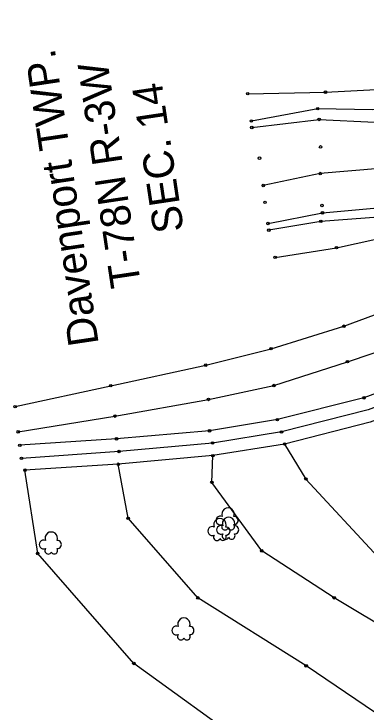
# Model space of a CAD drawing. Extents: x 21481721 to 21494985, y 8063982 to 8084842.
# Drawn here: x 21487805.3 to 21487944.9, y 8075079.6 to 8075356.1 of the extents above; entities that cross this region are included whole.
import ezdxf

# ---------------------------------------------------------------- set-up
doc = ezdxf.new("R2010")
doc.units = 0
for name, color, linetype in [('EXT_BL', 7, 'Continuous'), ('EXT_BNK', 7, 'Continuous'), ('EXT_C', 7, 'Continuous'), ('EXT_DU', 7, 'Continuous'), ('EXT_EP', 7, 'Continuous'), ('EXT_EW', 7, 'Continuous'), ('SurNaturalCells', 7, 'Continuous'), ('SurSurveyPoints', 7, 'Continuous'), ('Text', 7, 'Continuous')]:
    doc.layers.add(name, color=color, linetype=linetype)

msp = doc.modelspace()

# ---------------------------------------------------------------- linework, layer by layer
at = {"layer": 'EXT_BL'}
for points in [[(21487899.65, 8075311.12), (21487926.31, 8075314.33), (21487948.47, 8075313.19), (21487977.99, 8075319.96), (21488001.76, 8075319.05), (21488031.54, 8075324.07), (21488042.97, 8075326.03), (21488043.27, 8075340.95)], [(21487906.07, 8075273.12), (21487927.64, 8075277.31), (21487950.95, 8075279.4), (21487980.9, 8075284.8), (21488008.68, 8075286.71), (21488029.4, 8075287.81), (21488058.97, 8075290.19), (21488075.16, 8075293.91), (21488088.3, 8075291.86), (21488106.39, 8075293.3), (21488126.3, 8075293.36), (21488151.15, 8075297.33), (21488159.73, 8075298.37), (21488161.94, 8075298.12), (21488175.34, 8075296.97), (21488196.46, 8075301.74), (21488221.52, 8075304.21), (21488248.96, 8075305.15), (21488267.9, 8075305.62), (21488289.28, 8075304.94), (21488307.44, 8075304.08)], [(21487805.81, 8075200.57), (21487843.69, 8075208.86), (21487881.33, 8075216.99), (21487907.27, 8075223.5), (21487936.1, 8075232.4), (21487962.88, 8075242.3)], [(21487807.01, 8075190.56), (21487845.36, 8075196.81), (21487882.48, 8075203.41), (21487908.34, 8075208.9), (21487937.56, 8075218.37), (21487967.71, 8075228.44)], [(21487912.64, 8075185.75), (21487921.08, 8075171.87), (21487949.76, 8075140.97), (21487968.9, 8075133.2), (21487985.64, 8075128.01), (21488002.28, 8075121.82), (21488028.81, 8075113.01), (21488056.18, 8075112.57), (21488095.4, 8075114.28)], [(21488096.33, 8075080.43), (21488058.31, 8075085.68), (21488028.39, 8075089.85), (21487994.89, 8075100.27), (21487957.6, 8075109.66), (21487932.27, 8075124.86), (21487903.55, 8075143.43), (21487883.81, 8075170.57), (21487884.18, 8075181.16)], [(21488104.12, 8075053.16), (21488060.1, 8075057.21), (21488026.96, 8075060.99), (21487993.7, 8075067.26), (21487956.42, 8075073.93), (21487921.18, 8075097.88), (21487878.26, 8075124.79), (21487850.62, 8075156.33), (21487846.7, 8075177.74)], [(21488104, 8075024.19), (21488085.19, 8075025.67), (21488052.36, 8075029.9), (21488025.25, 8075031.54), (21487992.49, 8075034.52), (21487979.79, 8075035.75), (21487938.6, 8075047.85), (21487899.23, 8075065.23), (21487852.86, 8075098.85), (21487814.73, 8075142.38), (21487809.68, 8075175.41)]]:
    msp.add_lwpolyline(points, dxfattribs=at)
at = {"layer": 'EXT_BNK'}
for points in [[(21487898.01, 8075324.5), (21487928.88, 8075325.11), (21487948.89, 8075326.16), (21487970.53, 8075330.86), (21487994.52, 8075331.44), (21488017.06, 8075333.54), (21488035.32, 8075334.91), (21488036.46, 8075343.25), (21488040.24, 8075349.55), (21488050.96, 8075348.42), (21488057.24, 8075339.77), (21488065.83, 8075341.83), (21488068.85, 8075348.37), (21488082.03, 8075351.83), (21488097.42, 8075353.83), (21488117.6, 8075356.1), (21488135.76, 8075354.64), (21488140.54, 8075349.44), (21488146.46, 8075347.14), (21488156.97, 8075345.96), (21488161.69, 8075345.14), (21488170.03, 8075345.47)], [(21487908.87, 8075259.69), (21487933.23, 8075263.52), (21487956.58, 8075268.6), (21487979.62, 8075269.59), (21488001.82, 8075272.76), (21488020.49, 8075274.89), (21488039.84, 8075278.16), (21488058.97, 8075280.6), (21488063.52, 8075272.91), (21488069.32, 8075269.68), (21488076.91, 8075276.38), (21488091.45, 8075277.33), (21488107.46, 8075278.22), (21488125.4, 8075277.68), (21488139.82, 8075278.21), (21488147.98, 8075280.35), (21488159.45, 8075284.93), (21488168.49, 8075287.45)]]:
    msp.add_lwpolyline(points, dxfattribs=at)
at = {"layer": 'EXT_C'}
msp.add_lwpolyline([(21487975.58, 8075210.32), (21487945.74, 8075199.23), (21487911.38, 8075190.53), (21487884.07, 8075186.14), (21487846.99, 8075182.8), (21487808.32, 8075180.06)], dxfattribs=at)
at = {"layer": 'EXT_DU'}
msp.add_lwpolyline([(21488307.39, 8075321.37), (21488288.7, 8075319.02), (21488267.63, 8075319.82), (21488248.2, 8075317.75), (21488221.83, 8075319.3), (21488194.45, 8075316.05), (21488172.27, 8075318.52), (21488159.67, 8075317.11), (21488156.49, 8075316.85), (21488148.71, 8075316.9), (21488136.96, 8075316.3), (21488125.51, 8075314.02), (21488104.28, 8075315.5), (21488086.42, 8075313.27), (21488073.98, 8075312.2), (21488064.46, 8075308.6), (21488056.26, 8075305.21), (21488031.44, 8075308.76), (21488008.01, 8075298.78), (21487980.09, 8075304.29), (21487950.24, 8075294.88), (21487926.79, 8075292.88), (21487904.19, 8075288.15)], dxfattribs=at)
at = {"layer": 'EXT_EP'}
for points in [[(21487973.56, 8075214.92), (21487944.1, 8075204.06), (21487909.77, 8075195.4), (21487882.83, 8075190.99), (21487845.98, 8075187.82), (21487807.65, 8075185.24)], [(21487978.49, 8075206.22), (21487946.5, 8075194.4), (21487912.64, 8075185.75), (21487884.18, 8075181.16), (21487846.7, 8075177.74), (21487809.68, 8075175.41)]]:
    msp.add_lwpolyline(points, dxfattribs=at)
at = {"layer": 'EXT_EW'}
for points in [[(21487899.46, 8075313.71), (21487925.76, 8075318.59), (21487947.64, 8075318.24), (21487978.09, 8075323.74), (21488001.11, 8075322.79), (21488031.48, 8075326.72), (21488041.17, 8075329.67)], [(21488061.54, 8075287.11), (21488028.7, 8075284.05), (21488008.81, 8075283.32), (21487980.99, 8075281.5), (21487951.59, 8075275.76), (21487926.99, 8075273.93), (21487906.39, 8075270.48)]]:
    msp.add_lwpolyline(points, dxfattribs=at)
at = {"layer": 'SurNaturalCells'}
for centre, radius, start, end in [((21487890.22, 8075157.96), 2.46, 338.2051, 201.7949), ((21487886.99, 8075153.79), 2.46, 338.2051, 201.7949), ((21487887.2, 8075155.45), 1.76, 65.4824, 294.5175), ((21487890.44, 8075154.28), 2.46, 338.2051, 201.7949), ((21487892.61, 8075155.45), 1.6, 265.9982, 94.0018), ((21487883.97, 8075151.28), 1.76, 65.4824, 294.5175), ((21487887.43, 8075151.76), 1.76, 65.4824, 294.5175), ((21487889, 8075153.04), 1.34, 142.7501, 335.3223), ((21487889.38, 8075151.28), 1.6, 265.9982, 94.0018), ((21487891.41, 8075153.07), 1.34, 206.5242, 35.4033), ((21487892.84, 8075151.76), 1.6, 265.9982, 94.0018), ((21487820.11, 8075148.44), 2.46, 338.2051, 201.7949), ((21487885.77, 8075148.87), 1.34, 142.7501, 335.3223), ((21487888.18, 8075148.9), 1.34, 206.5242, 35.4033), ((21487889.23, 8075149.35), 1.34, 142.7501, 335.3223), ((21487891.64, 8075149.39), 1.34, 206.5242, 35.4033), ((21487817.1, 8075145.93), 1.76, 65.4824, 294.5175), ((21487822.51, 8075145.93), 1.6, 265.9982, 94.0018), ((21487818.9, 8075143.52), 1.34, 142.7501, 335.3223), ((21487821.31, 8075143.56), 1.34, 206.5242, 35.4033), ((21487872.7, 8075114.4), 2.46, 338.2051, 201.7949), ((21487869.69, 8075111.89), 1.76, 65.4824, 294.5175), ((21487875.1, 8075111.89), 1.6, 265.9982, 94.0018), ((21487871.48, 8075109.48), 1.34, 142.7501, 335.3223), ((21487873.89, 8075109.51), 1.34, 206.5242, 35.4033)]:
    msp.add_arc(centre, radius, start, end, dxfattribs=at)
at = {"layer": 'SurSurveyPoints'}
for centre in [(21487898.01, 8075324.5), (21487928.88, 8075325.11), (21487925.76, 8075318.59), (21487899.46, 8075313.71), (21487926.31, 8075314.33), (21487899.65, 8075311.12), (21487926.89, 8075303.44), (21487902.67, 8075298.97), (21487926.79, 8075292.88), (21487904.19, 8075288.15), (21487904.86, 8075281.49), (21487927.43, 8075280.23), (21487927.64, 8075277.31), (21487926.99, 8075273.93), (21487906.07, 8075273.12), (21487906.39, 8075270.48), (21487933.23, 8075263.52), (21487908.87, 8075259.69), (21487936.1, 8075232.4), (21487907.27, 8075223.5), (21487937.56, 8075218.37), (21487881.33, 8075216.99), (21487843.69, 8075208.86), (21487908.34, 8075208.9), (21487882.48, 8075203.41), (21487944.1, 8075204.06), (21487805.81, 8075200.57), (21487845.36, 8075196.81), (21487909.77, 8075195.4), (21487807.01, 8075190.56), (21487882.83, 8075190.99), (21487911.38, 8075190.53), (21487845.98, 8075187.82), (21487807.65, 8075185.24), (21487884.07, 8075186.14), (21487912.64, 8075185.75), (21487912.64, 8075185.75), (21487846.99, 8075182.8), (21487808.32, 8075180.06), (21487884.18, 8075181.16), (21487884.18, 8075181.16), (21487846.7, 8075177.74), (21487846.7, 8075177.74), (21487809.68, 8075175.41), (21487809.68, 8075175.41), (21487921.08, 8075171.87), (21487883.81, 8075170.57), (21487850.62, 8075156.33), (21487814.73, 8075142.38), (21487903.55, 8075143.43), (21487878.26, 8075124.79), (21487932.27, 8075124.86), (21487852.86, 8075098.85), (21487921.18, 8075097.88)]:
    msp.add_circle(centre, 0.5, dxfattribs=at)

# ---------------------------------------------------------------- texts
at = {"layer": 'Text'}
for s, p in [('Davenport TWP.', (21487838.97, 8075225.48)), ('T-78N R-3W', (21487855.73, 8075248.62)), ('SEC. 14', (21487872.71, 8075270.32))]:
    msp.add_text(s, height=12, rotation=98.5024, dxfattribs=at).set_placement(p)

doc.saveas('drawing.dxf')
